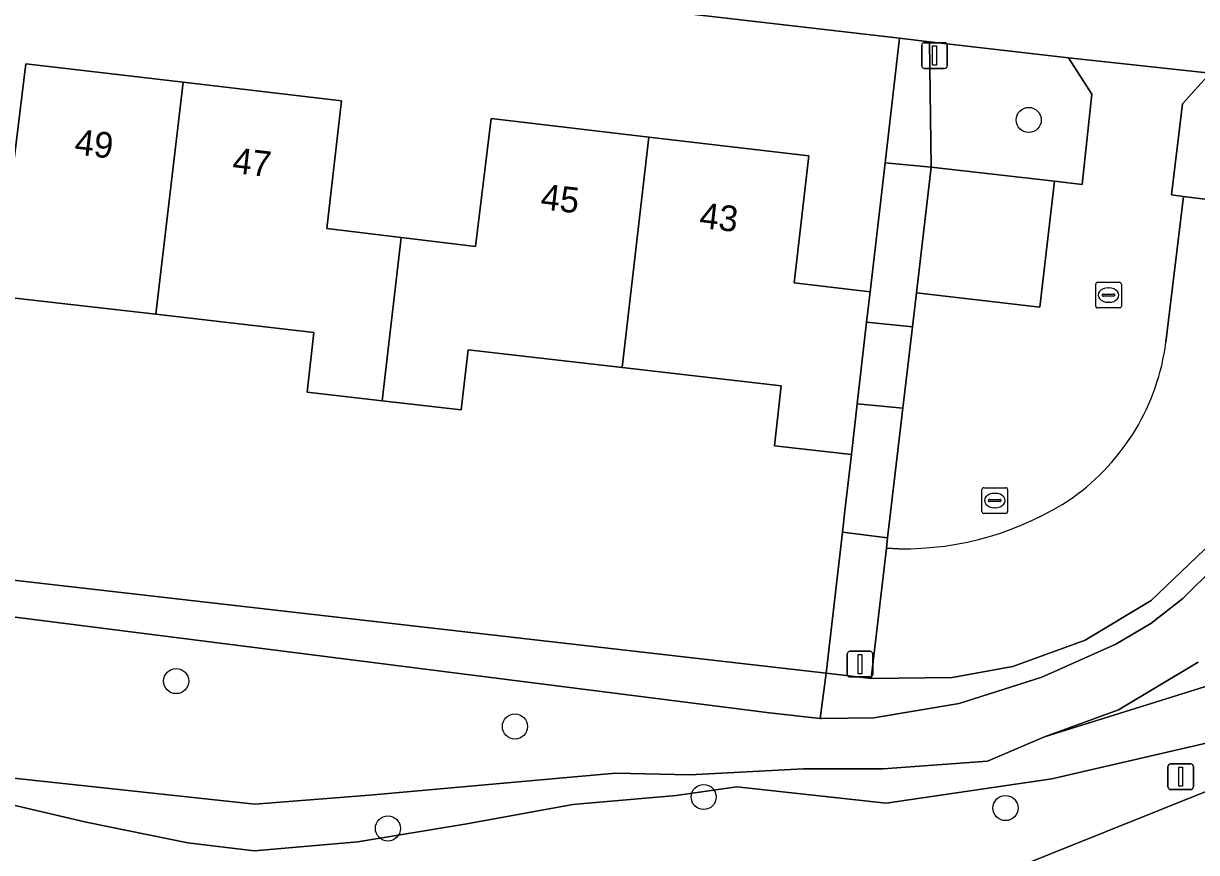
# Model space of a CAD drawing. Extents: x 161241 to 161758, y 384138 to 384885.
# Drawn here: x 161430.25 to 161475.93, y 384310.6 to 384342.9 of the extents above; entities that cross this region are included whole.
import ezdxf

# ---------------------------------------------------------------- set-up
doc = ezdxf.new("R2010")
doc.units = 0
for name, color, linetype in [('IMGEO_Boom', 7, 'Continuous'), ('IMGEO_Erf', 7, 'Continuous'), ('IMGEO_Groenvoorziening', 7, 'Continuous'), ('IMGEO_Kolk', 7, 'Continuous'), ('IMGEO_Lichtmast', 7, 'Continuous'), ('IMGEO_Pand', 7, 'Continuous'), ('IMGEO_Pand_nummerreeks', 7, 'Continuous'), ('IMGEO_Parkeervlak_open', 7, 'Continuous'), ('IMGEO_Rijbaan_lokaal_gesloten', 7, 'Continuous'), ('IMGEO_Rijbaan_lokaal_open', 7, 'Continuous')]:
    doc.layers.add(name, color=color, linetype=linetype)

msp = doc.modelspace()

# ---------------------------------------------------------------- linework, layer by layer
at = {"layer": 'IMGEO_Boom'}
for centre in [(161469.398, 384339.138), (161436.193, 384317.277), (161449.387, 384315.508), (161456.739, 384312.763), (161468.494, 384312.331), (161444.44, 384311.537)]:
    msp.add_circle(centre, 0.489, dxfattribs=at)
at = {"layer": 'IMGEO_Erf'}
for points in [[(161406.328, 384344.133), (161405.748, 384339.132), (161408.659, 384338.804), (161411.549, 384338.479), (161412.108, 384343.396), (161418.308, 384342.672), (161424.503, 384341.949), (161423.925, 384337.049), (161426.807, 384336.692), (161429.727, 384336.331), (161430.333, 384341.322), (161436.46, 384340.603), (161442.63, 384339.878), (161442.059, 384334.91), (161444.953, 384334.559), (161447.848, 384334.208), (161448.464, 384339.19), (161454.606, 384338.469), (161460.834, 384337.737), (161460.268, 384332.792), (161463.222, 384332.441), (161463.801, 384337.463), (161464.362, 384342.323), (161438.38, 384345.338)], [(161388.33, 384325.957), (161461.508, 384317.582), (161462.142, 384323.073), (161462.238, 384323.908), (161462.491, 384326.103), (161459.495, 384326.446), (161459.762, 384328.78), (161453.559, 384329.49), (161447.561, 384330.177), (161447.293, 384327.842), (161444.211, 384328.195), (161441.292, 384328.529), (161441.559, 384330.863), (161435.407, 384331.567), (161429.348, 384332.261)]]:
    msp.add_lwpolyline(points, dxfattribs=at)
at = {"layer": 'IMGEO_Groenvoorziening'}
for points in [[(161465.534, 384342.187), (161464.464, 384342.311), (161464.362, 384342.323), (161463.801, 384337.463), (161465.598, 384337.292)], [(161471.862, 384340.148), (161470.952, 384341.558), (161465.534, 384342.187), (161465.598, 384337.292), (161470.402, 384336.75), (161471.473, 384336.629)], [(161465.598, 384337.292), (161463.801, 384337.463), (161463.222, 384332.441), (161463.085, 384331.257), (161464.867, 384331.074), (161465.023, 384332.401)], [(161464.867, 384331.074), (161463.085, 384331.257), (161462.718, 384328.074), (161464.495, 384327.906)], [(161464.495, 384327.906), (161462.718, 384328.074), (161462.491, 384326.103), (161462.238, 384323.908), (161462.142, 384323.073), (161463.902, 384322.859)], [(161461.281, 384315.825), (161461.326, 384315.82), (161463.36, 384315.849), (161466.691, 384316.41), (161469.912, 384317.429), (161472.796, 384318.719), (161474.159, 384319.524), (161475.405, 384320.5), (161476.658, 384321.748), (161477.771, 384323.123), (161478.721, 384324.615), (161478.94, 384325.084), (161478.375, 384325.383), (161476.526, 384322.68), (161474.16, 384320.415), (161471.59, 384318.875), (161468.777, 384317.844), (161466.411, 384317.413), (161463.259, 384317.382), (161461.622, 384317.569), (161461.508, 384317.582)], [(161463.855, 384322.457), (161463.902, 384322.859), (161462.142, 384323.073), (161461.508, 384317.582), (161461.622, 384317.569), (161463.259, 384317.382)]]:
    msp.add_lwpolyline(points, close=True, dxfattribs=at)
for points in [[(161476.463, 384340.955), (161475.384, 384339.768), (161474.953, 384336.215), (161475.431, 384336.155), (161480.406, 384335.536)], [(161383.959, 384302.494), (161386.987, 384306.894), (161389.478, 384309.685), (161390.337, 384311.694), (161389.037, 384313.944), (161385.772, 384318.093), (161385.994, 384320.251), (161387.855, 384323.519), (161398.386, 384323.765), (161459.305, 384316.043), (161461.281, 384315.825), (161461.508, 384317.582), (161388.33, 384325.957), (161386.343, 384326.184), (161383.222, 384299.937)], [(161476.658, 384321.748), (161475.405, 384320.5), (161474.159, 384319.524), (161472.796, 384318.719), (161469.912, 384317.429), (161466.691, 384316.41), (161463.36, 384315.849), (161461.326, 384315.82), (161461.281, 384315.825), (161459.305, 384316.043), (161398.386, 384323.765)], [(161466.078, 384308.877), (161495.528, 384320.69)], [(161426.121, 384313.903), (161439.251, 384312.48), (161443.725, 384312.838), (161453.3, 384313.687), (161456.2, 384313.632), (161460.625, 384313.859), (161463.734, 384313.859), (161467.796, 384314.154), (161470.006, 384315.1), (161472.889, 384316.156), (161475.991, 384318.015)], [(161475.991, 384318.015), (161472.889, 384316.156), (161470.006, 384315.1), (161477.282, 384317.376)], [(161477.282, 384317.376), (161470.006, 384315.1), (161467.796, 384314.154), (161463.734, 384313.859), (161460.625, 384313.859), (161456.2, 384313.632), (161453.3, 384313.687), (161443.725, 384312.838), (161439.251, 384312.48), (161426.121, 384313.903)], [(161428.913, 384312.669), (161432.686, 384311.783), (161436.652, 384310.973), (161439.237, 384310.669), (161443.269, 384311.021), (161447.518, 384311.722), (161451.642, 384312.465), (161455.665, 384312.818), (161458.031, 384313.16), (161463.848, 384312.52), (161470.293, 384313.473), (161477.373, 384315.107)], [(161477.373, 384315.107), (161470.293, 384313.473), (161463.848, 384312.52), (161458.031, 384313.16), (161455.665, 384312.818), (161451.642, 384312.465), (161447.518, 384311.722), (161443.269, 384311.021), (161439.237, 384310.669), (161436.652, 384310.973), (161432.686, 384311.783), (161428.913, 384312.669)]]:
    msp.add_lwpolyline(points, dxfattribs=at)
at = {"layer": 'IMGEO_Kolk'}
for p, q in [((161472.005, 384331.888), (161472.005, 384332.74)), ((161472.08, 384332.814), (161472.932, 384332.814)), ((161472.493, 384332.594), (161472.518, 384332.594)), ((161473.006, 384332.74), (161473.006, 384331.888)), ((161472.264, 384332.308), (161472.264, 384332.32)), ((161472.702, 384332.271), (161472.304, 384332.271)), ((161472.307, 384332.357), (161472.705, 384332.357)), ((161472.748, 384332.32), (161472.748, 384332.308)), ((161472.932, 384331.814), (161472.08, 384331.814)), ((161472.516, 384332.034), (161472.491, 384332.034)), ((161467.65, 384324.812), (161468.502, 384324.812)), ((161467.575, 384323.886), (161467.575, 384324.738)), ((161467.877, 384324.355), (161468.275, 384324.355)), ((161468.063, 384324.592), (161468.088, 384324.592)), ((161468.576, 384324.738), (161468.576, 384323.886)), ((161467.834, 384324.306), (161467.834, 384324.318)), ((161468.272, 384324.269), (161467.874, 384324.269)), ((161468.086, 384324.032), (161468.061, 384324.032)), ((161468.318, 384324.318), (161468.318, 384324.306)), ((161468.502, 384323.812), (161467.65, 384323.812))]:
    msp.add_line(p, q, dxfattribs=at)
for points in [[(161472.005, 384331.888), (161472.005, 384332.74)], [(161472.08, 384332.814), (161472.932, 384332.814)], [(161473.006, 384332.74), (161473.006, 384331.888)], [(161472.932, 384331.814), (161472.08, 384331.814)], [(161467.65, 384324.812), (161468.502, 384324.812)], [(161467.575, 384323.886), (161467.575, 384324.738)], [(161468.576, 384324.738), (161468.576, 384323.886)], [(161468.502, 384323.812), (161467.65, 384323.812)]]:
    msp.add_lwpolyline(points, dxfattribs=at)
for centre, radius, start, end in [((161472.082, 384332.738), 0.0765, 91.552, 178.448), ((161472.082, 384332.738), 0.0765, 91.552, 178.448), ((161472.93, 384332.738), 0.0765, 1.552, 88.448), ((161472.93, 384332.738), 0.0765, 1.552, 88.448), ((161472.304, 384332.317), 0.0403, 85.8775, 175.7526), ((161472.301, 384332.307), 0.0366, 178.938, 274.7102), ((161472.705, 384332.314), 0.043, 264.8664, 352.4533), ((161472.709, 384332.319), 0.0386, 1.7309, 96.639), ((161472.082, 384331.89), 0.0765, 181.552, 268.448), ((161472.082, 384331.89), 0.0765, 181.552, 268.448), ((161472.93, 384331.89), 0.0765, 271.552, 358.448), ((161472.93, 384331.89), 0.0765, 271.552, 358.448), ((161467.652, 384324.736), 0.0765, 91.552, 178.448), ((161467.652, 384324.736), 0.0765, 91.552, 178.448), ((161468.5, 384324.736), 0.0765, 1.552, 88.448), ((161468.5, 384324.736), 0.0765, 1.552, 88.448), ((161467.874, 384324.315), 0.0403, 85.8775, 175.7526), ((161468.279, 384324.317), 0.0386, 1.7309, 96.639), ((161467.652, 384323.888), 0.0765, 181.552, 268.448), ((161467.652, 384323.888), 0.0765, 181.552, 268.448), ((161467.871, 384324.305), 0.0366, 178.938, 274.7102), ((161468.275, 384324.312), 0.043, 264.8664, 352.4533), ((161468.5, 384323.888), 0.0765, 271.552, 358.448), ((161468.5, 384323.888), 0.0765, 271.552, 358.448)]:
    msp.add_arc(centre, radius, start, end, dxfattribs=at)
for centre, major_axis, ratio, start_param, end_param in [((161472.492, 384332.314), (-0.387, 0.002), 0.722429, 4.712389, 7.853982), ((161472.517, 384332.314), (-0.39, 0.002), 0.717154, 1.570796, 4.712389), ((161468.062, 384324.312), (-0.387, 0.002), 0.722429, 4.712389, 7.853982), ((161468.087, 384324.312), (-0.39, 0.002), 0.717154, 1.570796, 4.712389)]:
    msp.add_ellipse(centre, major_axis=major_axis, ratio=ratio, start_param=start_param, end_param=end_param, dxfattribs=at)
at = {"layer": 'IMGEO_Lichtmast'}
for p, q in [((161465.233, 384341.247), (161465.233, 384342.047)), ((161465.233, 384342.047), (161465.233, 384341.247)), ((161465.333, 384342.147), (161466.123, 384342.147)), ((161466.123, 384342.147), (161465.333, 384342.147)), ((161466.223, 384342.047), (161466.223, 384341.247)), ((161466.223, 384341.247), (161466.223, 384342.047)), ((161466.123, 384341.147), (161465.333, 384341.147)), ((161465.333, 384341.147), (161466.123, 384341.147)), ((161462.431, 384318.438), (161463.221, 384318.438)), ((161463.221, 384318.438), (161462.431, 384318.438)), ((161462.331, 384317.538), (161462.331, 384318.338)), ((161462.331, 384318.338), (161462.331, 384317.538)), ((161463.321, 384318.338), (161463.321, 384317.538)), ((161463.321, 384317.538), (161463.321, 384318.338)), ((161463.221, 384317.438), (161462.431, 384317.438)), ((161462.431, 384317.438), (161463.221, 384317.438)), ((161474.821, 384313.153), (161474.821, 384313.953)), ((161474.821, 384313.953), (161474.821, 384313.153)), ((161474.921, 384314.053), (161475.711, 384314.053)), ((161475.711, 384314.053), (161474.921, 384314.053)), ((161475.811, 384313.953), (161475.811, 384313.153)), ((161475.811, 384313.153), (161475.811, 384313.953)), ((161475.711, 384313.053), (161474.921, 384313.053)), ((161474.921, 384313.053), (161475.711, 384313.053))]:
    msp.add_line(p, q, dxfattribs=at)
for points in [[(161465.653, 384342.022), (161465.803, 384342.022), (161465.803, 384341.272), (161465.653, 384341.272), (161465.653, 384342.022)], [(161462.751, 384318.313), (161462.901, 384318.313), (161462.901, 384317.563), (161462.751, 384317.563), (161462.751, 384318.313)], [(161475.241, 384313.928), (161475.391, 384313.928), (161475.391, 384313.178), (161475.241, 384313.178), (161475.241, 384313.928)]]:
    msp.add_lwpolyline(points, dxfattribs=at)
for centre, start, end in [((161465.333, 384342.047), 90, 180), ((161465.333, 384342.047), 90, 180), ((161466.123, 384342.047), 0, 90), ((161466.123, 384342.047), 360, 90), ((161465.333, 384341.247), 180, 270), ((161465.333, 384341.247), 180, 270), ((161466.123, 384341.247), 270, 0), ((161466.123, 384341.247), 270, 0), ((161462.431, 384318.338), 90, 180), ((161462.431, 384318.338), 90, 180), ((161463.221, 384318.338), 0, 90), ((161463.221, 384318.338), 360, 90), ((161462.431, 384317.538), 180, 270), ((161462.431, 384317.538), 180, 270), ((161463.221, 384317.538), 270, 0), ((161463.221, 384317.538), 270, 0), ((161474.921, 384313.953), 90, 180), ((161474.921, 384313.953), 90, 180), ((161475.711, 384313.953), 0, 90), ((161475.711, 384313.953), 360, 90), ((161474.921, 384313.153), 180, 270), ((161474.921, 384313.153), 180, 270), ((161475.711, 384313.153), 270, 0), ((161475.711, 384313.153), 270, 0)]:
    msp.add_arc(centre, 0.1, start, end, dxfattribs=at)
at = {"layer": 'IMGEO_Pand'}
for points in [[(161436.46, 384340.603), (161430.333, 384341.322), (161429.727, 384336.331), (161426.807, 384336.692), (161426.059, 384330.272), (161429.08, 384329.926), (161429.348, 384332.261), (161435.407, 384331.567)], [(161435.407, 384331.567), (161441.559, 384330.863), (161441.292, 384328.529), (161444.211, 384328.195), (161444.953, 384334.559), (161442.059, 384334.91), (161442.63, 384339.878), (161436.46, 384340.603)], [(161454.606, 384338.469), (161448.464, 384339.19), (161447.848, 384334.208), (161444.953, 384334.559), (161444.211, 384328.195), (161447.293, 384327.842), (161447.561, 384330.177), (161453.559, 384329.49)], [(161460.268, 384332.792), (161460.834, 384337.737), (161454.606, 384338.469), (161453.559, 384329.49), (161459.762, 384328.78), (161459.495, 384326.446), (161462.491, 384326.103), (161462.718, 384328.074), (161463.085, 384331.257), (161463.222, 384332.441)]]:
    msp.add_lwpolyline(points, close=True, dxfattribs=at)
at = {"layer": 'IMGEO_Parkeervlak_open'}
msp.add_lwpolyline([(161465.023, 384332.401), (161469.825, 384331.846), (161470.402, 384336.75), (161465.598, 384337.292)], close=True, dxfattribs=at)
msp.add_lwpolyline([(161464.338, 384322.435), (161463.855, 384322.457), (161463.259, 384317.382), (161466.411, 384317.413), (161468.777, 384317.844), (161471.59, 384318.875), (161474.16, 384320.415), (161476.526, 384322.68), (161478.375, 384325.383), (161479.252, 384327.524), (161479.717, 384329.79), (161480.406, 384335.536), (161475.431, 384336.155), (161474.74, 384330.481)], dxfattribs=at)
for centre, radius, start, end in [((161465.977, 384331.616), 8.837, 305.4513, 352.6184), ((161464.537, 384334.284), 11.851, 269.038, 303.6411)]:
    msp.add_arc(centre, radius, start, end, dxfattribs=at)
at = {"layer": 'IMGEO_Rijbaan_lokaal_gesloten'}
msp.add_lwpolyline([(161493.996, 384316.698), (161495.528, 384320.69), (161466.078, 384308.877)], dxfattribs=at)
at = {"layer": 'IMGEO_Rijbaan_lokaal_open'}
msp.add_lwpolyline([(161490.204, 384343.929), (161438.91, 384349.892), (161438.38, 384345.338), (161464.362, 384342.323), (161464.464, 384342.311), (161465.534, 384342.187), (161470.952, 384341.558), (161476.463, 384340.955), (161489.705, 384339.472)], close=True, dxfattribs=at)
for points in [[(161475.431, 384336.155), (161474.953, 384336.215), (161475.384, 384339.768), (161476.463, 384340.955), (161470.952, 384341.558), (161471.862, 384340.148), (161471.473, 384336.629), (161470.402, 384336.75), (161469.825, 384331.846), (161465.023, 384332.401), (161464.867, 384331.074), (161464.495, 384327.906), (161463.902, 384322.859), (161463.855, 384322.457), (161464.338, 384322.435)], [(161474.74, 384330.481), (161475.431, 384336.155)]]:
    msp.add_lwpolyline(points, dxfattribs=at)
for centre, radius, start, end in [((161465.977, 384331.616), 8.837, 305.4513, 352.6184), ((161464.537, 384334.284), 11.851, 269.038, 303.6411)]:
    msp.add_arc(centre, radius, start, end, dxfattribs=at)

# ---------------------------------------------------------------- texts
at = {"layer": 'IMGEO_Pand_nummerreeks'}
for s, rotation, p in [('49', 353.3026, (161432.204, 384337.8)), ('47', 353.3026, (161438.353, 384337.078)), ('45', 353.3006, (161450.353, 384335.666)), ('43', 353.3021, (161456.538, 384334.94))]:
    msp.add_text(s, height=1, rotation=rotation, dxfattribs=at).set_placement(p)

doc.saveas('drawing.dxf')
